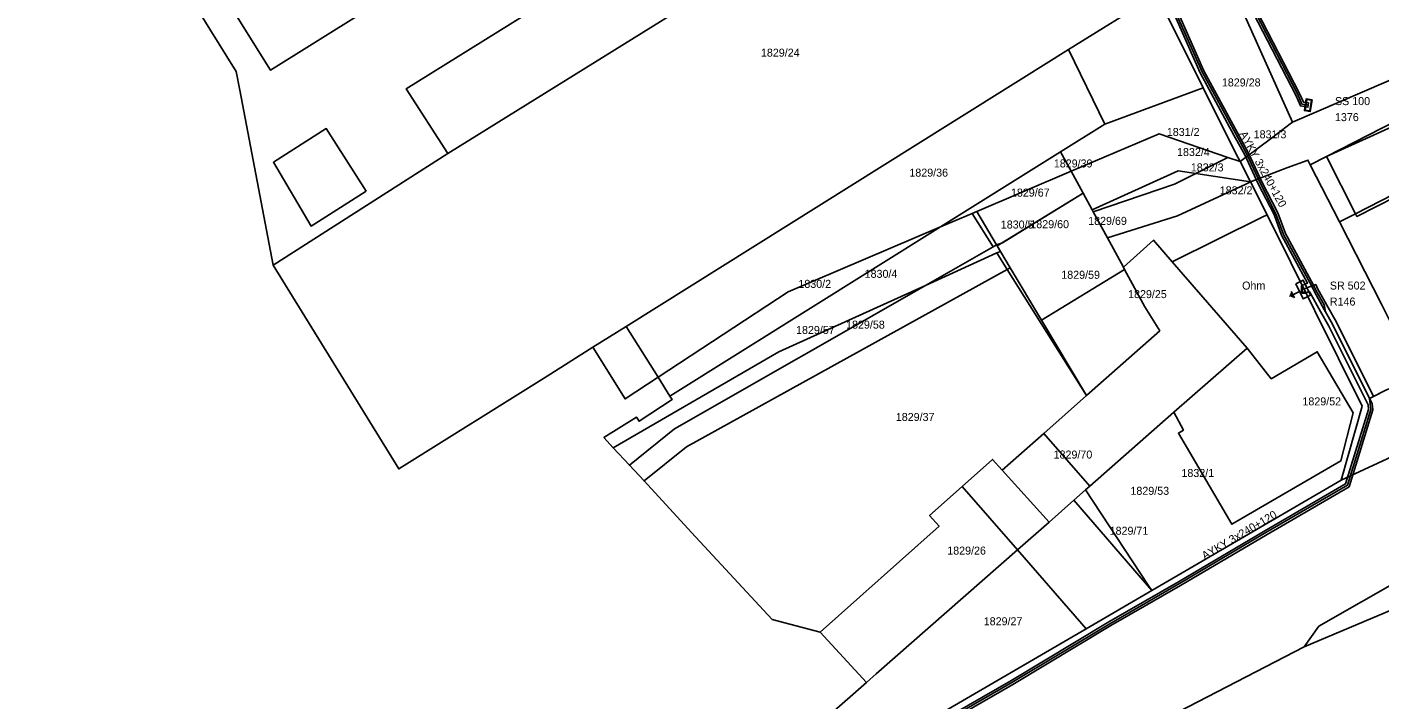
# Model space of a CAD drawing. Extents: x -793400 to -756198, y -1074141 to -1042963.
# Drawn here: x -783799.4 to -783672.6, y -1065170.5 to -1065107.5 of the extents above; entities that cross this region are included whole.
import ezdxf

# ---------------------------------------------------------------- set-up
doc = ezdxf.new("R2010")
doc.units = 0
for name, color, linetype in [('Parcela', 7, 'Continuous'), ('Popiskový text - Parcela', 7, 'Continuous'), ('Popiskový text - Přípojková skříň nn - SJZ', 7, 'Continuous'), ('Popiskový text - Přípojková skříň nn - Typ', 7, 'Continuous'), ('Popiskový text - Rozpojovací skříň nn - SJZ', 7, 'Continuous'), ('Popiskový text - Rozpojovací skříň nn - Typ', 7, 'Continuous'), ('Popiskový text - Uzemnění - Odpor', 7, 'Continuous'), ('Popiskový text - Vedení nn kabelové', 7, 'Continuous'), ('Skříň', 7, 'Continuous'), ('Spojnice nn', 7, 'Continuous'), ('Stavební objekt', 7, 'Continuous'), ('Uzemnění', 7, 'Continuous'), ('Vedení nn kabelové', 7, 'Continuous')]:
    doc.layers.add(name, color=color, linetype=linetype)

msp = doc.modelspace()

# ---------------------------------------------------------------- linework, layer by layer
at = {"layer": 'Parcela'}
for points in [[(-783743.49, -1064990.04), (-783721.39, -1065031.49), (-783712.22, -1065050.17), (-783710.41, -1065053.85), (-783709.53, -1065055.65), (-783703.49, -1065067.95), (-783696.3, -1065082.59), (-783693.78, -1065087.45), (-783688.13, -1065100.02), (-783687.19, -1065102.12), (-783680.77, -1065116.4), (-783681, -1065116.57), (-783682.63, -1065117.8), (-783685.7, -1065120.1), (-783686.08, -1065119.34), (-783689.14, -1065113.18), (-783693.49, -1065104.44), (-783703.53, -1065084.3), (-783706.78, -1065077.78), (-783710.42, -1065070.95), (-783718.74, -1065055.31), (-783724.35, -1065043.92), (-783728.08, -1065036.33), (-783742.64, -1065007.02)], [(-783671.05, -1065116.27), (-783677.6, -1065119.63), (-783679.11, -1065120.41), (-783679.34, -1065119.96), (-783679.42, -1065119.99), (-783681.3, -1065120.7), (-783684.71, -1065122), (-783685.7, -1065120.1), (-783682.63, -1065117.8), (-783681, -1065116.57), (-783680.77, -1065116.4), (-783641.16, -1065099.33)], [(-783658.1, -1065152.09), (-783678.31, -1065163.62), (-783679.68, -1065165.57), (-783702.33, -1065177.28), (-783718.17, -1065186.15), (-783811.05, -1065243.68), (-783813.45, -1065244.74), (-783817.37, -1065243.24), (-783821.65, -1065245.66), (-783820.85, -1065243.75), (-783819.75, -1065241.1), (-783815.59, -1065239.1), (-783811.96, -1065230.63), (-783767.51, -1065209.46), (-783747.03, -1065195.25), (-783744.03, -1065193.23), (-783722.17, -1065178.5), (-783720.51, -1065177.39), (-783721.11, -1065176.1), (-783713.42, -1065171.62), (-783700.12, -1065163.87), (-783693.97, -1065160.29), (-783676.21, -1065149.95), (-783668.48, -1065146.36)], [(-783894.54, -1065298.16), (-783877.6, -1065288.64), (-783876.01, -1065286.99), (-783878.67, -1065284.84), (-783879.31, -1065284.33), (-783882.85, -1065281.51), (-783884.25, -1065280.8), (-783884.72, -1065280.35), (-783886.64, -1065279.77), (-783889.27, -1065279.67), (-783889.47, -1065279.21), (-783885.7, -1065277.91), (-783869.62, -1065270.55), (-783867.95, -1065269.78), (-783847.11, -1065258.93), (-783821.65, -1065245.66), (-783817.37, -1065243.24), (-783813.45, -1065244.74), (-783811.05, -1065243.68), (-783718.17, -1065186.15), (-783702.33, -1065177.28), (-783679.68, -1065165.57), (-783638.54, -1065148.19)]]:
    msp.add_lwpolyline(points, dxfattribs=at)
for points in [[(-783624.81, -1065029.37), (-783608.24, -1065050.49), (-783609.02, -1065051.01), (-783614.97, -1065042.05), (-783620.25, -1065045.55), (-783614.53, -1065054.22), (-783645.96, -1065074.99), (-783640.19, -1065083.64), (-783609.28, -1065062.42), (-783602.2, -1065072.93), (-783596.89, -1065069.32), (-783607.37, -1065053.5), (-783606.59, -1065052.98), (-783598.14, -1065065.66), (-783595.45, -1065069.7), (-783618.75, -1065083), (-783634.61, -1065095.52), (-783641.16, -1065099.33), (-783680.77, -1065116.4), (-783687.19, -1065102.12), (-783688.13, -1065100.02), (-783693.78, -1065087.45), (-783696.3, -1065082.59)], [(-783706.78, -1065077.78), (-783763.85, -1065113.27), (-783759.96, -1065119.35), (-783776.33, -1065129.79), (-783779.45, -1065113.42), (-783779.79, -1065111.66), (-783782.26, -1065107.68), (-783797.2, -1065083.56), (-783794.93, -1065082.14), (-783776.57, -1065111.53), (-783750.64, -1065095.32), (-783756.62, -1065085.78), (-783751.21, -1065082.35), (-783749.58, -1065084.96), (-783741.18, -1065079.7), (-783740.15, -1065081.36), (-783741.89, -1065082.45), (-783738.3, -1065088.24), (-783710.42, -1065070.95)], [(-783693.49, -1065104.44), (-783689.14, -1065113.18), (-783698.37, -1065116.59), (-783701.76, -1065109.61), (-783706.21, -1065112.39), (-783713.05, -1065116.67), (-783743.22, -1065135.54), (-783740.24, -1065140.31), (-783743.33, -1065142.34), (-783746.36, -1065137.5), (-783750.65, -1065140.19), (-783764.55, -1065148.9), (-783776.33, -1065129.79), (-783759.96, -1065119.35), (-783763.85, -1065113.27), (-783706.78, -1065077.78), (-783703.53, -1065084.3)], [(-783728.04, -1065132.29), (-783740.24, -1065140.31), (-783743.22, -1065135.54), (-783713.05, -1065116.67), (-783706.21, -1065112.39), (-783701.76, -1065109.61), (-783698.37, -1065116.59), (-783702.51, -1065119.18), (-783713.76, -1065126.22)], [(-783689.14, -1065113.18), (-783686.08, -1065119.34), (-783685.7, -1065120.1), (-783686.83, -1065119.71), (-783693.27, -1065117.51), (-783701.51, -1065121.01), (-783702.51, -1065119.18), (-783698.37, -1065116.59)], [(-783664.69, -1065115.43), (-783662.2, -1065121.16), (-783668.56, -1065118.67), (-783669.82, -1065116.11), (-783677.6, -1065119.63), (-783671.05, -1065116.27), (-783670.46, -1065116.02), (-783665.66, -1065113.94)], [(-783767.61, -1065122.87), (-783771.34, -1065117.01), (-783776.3, -1065120.16), (-783772.76, -1065126.15)], [(-783668, -1065121.84), (-783666.8, -1065124.7), (-783662.43, -1065122.81), (-783661.97, -1065123.9), (-783659.86, -1065128.84), (-783658.99, -1065128.48), (-783655.16, -1065137.64), (-783661.5, -1065141.32), (-783667.76, -1065126.41), (-783667.4, -1065126.25), (-783669.21, -1065122.45), (-783674.74, -1065125.24), (-783674.87, -1065124.98), (-783676.39, -1065125.75), (-783679.11, -1065120.41), (-783677.6, -1065119.63), (-783669.82, -1065116.11), (-783668.56, -1065118.67), (-783667.19, -1065121.43)], [(-783686.83, -1065119.71), (-783689.84, -1065121.22), (-783691.51, -1065120.97), (-783699.55, -1065124.62), (-783700.4, -1065123.05), (-783701.51, -1065121.01), (-783693.27, -1065117.51)], [(-783700.4, -1065123.05), (-783708.45, -1065128), (-783708.52, -1065127.89), (-783710.37, -1065124.78), (-783710.8, -1065124.96), (-783713.76, -1065126.22), (-783702.51, -1065119.18), (-783701.51, -1065121.01)], [(-783691.85, -1065122.23), (-783699.45, -1065124.81), (-783699.55, -1065124.62), (-783691.51, -1065120.97), (-783689.84, -1065121.22)], [(-783685.7, -1065120.1), (-783684.71, -1065122), (-783689.84, -1065121.22), (-783686.83, -1065119.71)], [(-783668.48, -1065146.36), (-783676.21, -1065149.95), (-783674.25, -1065143), (-783683.17, -1065125.09), (-783684.71, -1065122), (-783681.3, -1065120.7), (-783679.42, -1065119.99), (-783679.34, -1065119.96), (-783679.11, -1065120.41), (-783676.39, -1065125.75), (-783672.45, -1065133.46), (-783671.53, -1065135.28), (-783668.93, -1065140.36), (-783664.13, -1065142.85), (-783663.26, -1065143.94), (-783667.48, -1065145.9)], [(-783691.57, -1065125.19), (-783698.13, -1065127.23), (-783699.45, -1065124.81), (-783691.85, -1065122.23), (-783689.84, -1065121.22), (-783684.71, -1065122), (-783685.15, -1065122.22)], [(-783683.61, -1065125.31), (-783692.06, -1065129.49), (-783693.82, -1065127.46), (-783696.62, -1065130), (-783698.13, -1065127.23), (-783691.57, -1065125.19), (-783685.15, -1065122.22), (-783684.71, -1065122), (-783683.17, -1065125.09)], [(-783696.52, -1065130.2), (-783704.3, -1065134.97), (-783707.23, -1065130.05), (-783708.15, -1065128.51), (-783708.45, -1065128), (-783700.4, -1065123.05), (-783699.55, -1065124.62), (-783699.45, -1065124.81), (-783698.13, -1065127.23), (-783696.62, -1065130)], [(-783669.21, -1065122.45), (-783667.4, -1065126.25), (-783667.76, -1065126.41), (-783661.5, -1065141.32), (-783664.13, -1065142.85), (-783668.93, -1065140.36), (-783671.53, -1065135.28), (-783672.45, -1065133.46), (-783676.39, -1065125.75), (-783674.87, -1065124.98), (-783674.74, -1065125.24)], [(-783708.52, -1065127.89), (-783708.85, -1065128.08), (-783710.8, -1065124.96), (-783710.37, -1065124.78)], [(-783728.92, -1065137.93), (-783744.44, -1065146.92), (-783745.32, -1065145.96), (-783742.26, -1065144.05), (-783742.02, -1065144.43), (-783738.93, -1065142.4), (-783739.13, -1065142.09), (-783713.76, -1065126.22), (-783710.8, -1065124.96), (-783708.85, -1065128.08), (-783715.18, -1065131.7)], [(-783683.17, -1065125.09), (-783674.25, -1065143), (-783676.21, -1065149.95), (-783693.97, -1065160.29), (-783694.31, -1065159.77), (-783700.17, -1065150.86), (-783699.76, -1065150.5), (-783691.89, -1065143.59), (-783691, -1065145.26), (-783691.47, -1065145.54), (-783686.46, -1065154.07), (-783676.25, -1065148.14), (-783675.1, -1065143.65), (-783678.46, -1065137.91), (-783682.77, -1065140.44), (-783685.04, -1065137.58), (-783692.06, -1065129.49), (-783683.61, -1065125.31)], [(-783713.76, -1065126.22), (-783739.13, -1065142.09), (-783740.24, -1065140.31), (-783728.04, -1065132.29)], [(-783708.48, -1065128.66), (-783715.18, -1065131.7), (-783708.85, -1065128.08), (-783708.52, -1065127.89), (-783708.45, -1065128), (-783708.15, -1065128.51)], [(-783707.23, -1065130.05), (-783707.51, -1065130.2), (-783708.48, -1065128.66), (-783708.15, -1065128.51)], [(-783685.04, -1065137.58), (-783682.77, -1065140.44), (-783678.46, -1065137.91), (-783675.1, -1065143.65), (-783676.25, -1065148.14), (-783686.46, -1065154.07), (-783691.47, -1065145.54), (-783691, -1065145.26), (-783691.89, -1065143.59), (-783699.76, -1065150.5), (-783704.09, -1065145.57), (-783700.09, -1065142.03), (-783693.22, -1065135.95), (-783694.61, -1065133.7), (-783696.52, -1065130.2), (-783696.62, -1065130), (-783693.82, -1065127.46), (-783692.06, -1065129.49)], [(-783737.58, -1065146.81), (-783741.56, -1065150.02), (-783742.92, -1065148.55), (-783738.71, -1065145.15), (-783715.18, -1065131.7), (-783708.48, -1065128.66), (-783707.51, -1065130.2)], [(-783704.09, -1065145.57), (-783707.98, -1065149.02), (-783708.89, -1065148.01), (-783711.73, -1065150.54), (-783714.79, -1065153.27), (-783713.9, -1065154.27), (-783725.04, -1065164.2), (-783729.54, -1065163.01), (-783737.1, -1065154.85), (-783741.56, -1065150.02), (-783737.58, -1065146.81), (-783707.51, -1065130.2), (-783700.09, -1065142.03)], [(-783704.3, -1065134.97), (-783700.09, -1065142.03), (-783707.51, -1065130.2), (-783707.23, -1065130.05)], [(-783693.22, -1065135.95), (-783700.09, -1065142.03), (-783704.3, -1065134.97), (-783696.52, -1065130.2), (-783694.61, -1065133.7)], [(-783738.71, -1065145.15), (-783742.92, -1065148.55), (-783744.44, -1065146.92), (-783728.92, -1065137.93), (-783715.18, -1065131.7)], [(-783704.09, -1065145.57), (-783699.76, -1065150.5), (-783700.17, -1065150.86), (-783701.26, -1065151.82), (-783703.6, -1065153.87), (-783706.56, -1065156.47), (-783711.73, -1065150.54), (-783708.89, -1065148.01), (-783707.98, -1065149.02)], [(-783638.54, -1065148.19), (-783679.68, -1065165.57), (-783678.31, -1065163.62), (-783658.1, -1065152.09), (-783638.24, -1065146.37)], [(-783719.81, -1065168.1), (-783720.72, -1065168.9), (-783725.04, -1065164.2), (-783713.9, -1065154.27), (-783714.79, -1065153.27), (-783711.73, -1065150.54), (-783706.56, -1065156.47)], [(-783694.31, -1065159.77), (-783693.97, -1065160.29), (-783694.38, -1065159.81), (-783701.26, -1065151.82), (-783700.17, -1065150.86)], [(-783693.97, -1065160.29), (-783700.12, -1065163.87), (-783700.52, -1065163.41), (-783706.56, -1065156.47), (-783703.6, -1065153.87), (-783701.26, -1065151.82), (-783694.38, -1065159.81)], [(-783713.42, -1065171.62), (-783721.11, -1065176.1), (-783721.36, -1065175.66), (-783723.31, -1065174.64), (-783725.03, -1065172.69), (-783720.72, -1065168.9), (-783719.81, -1065168.1), (-783706.56, -1065156.47), (-783700.52, -1065163.41), (-783700.12, -1065163.87)]]:
    msp.add_lwpolyline(points, close=True, dxfattribs=at)
at = {"layer": 'Skříň'}
for points in [[(-783678.94, -1065114.3), (-783679.11, -1065115.41), (-783679.66, -1065115.32), (-783679.49, -1065114.21)], [(-783679.16, -1065115.34), (-783679, -1065114.34), (-783679.45, -1065114.28), (-783679.6, -1065115.28)], [(-783680.48, -1065131.55), (-783679.79, -1065132.97), (-783679.08, -1065132.63), (-783679.77, -1065131.21)]]:
    msp.add_lwpolyline(points, close=True, dxfattribs=at)
at = {"layer": 'Spojnice nn'}
for points in [[(-783695.55, -1065082.08), (-783694.73, -1065084.09), (-783693.68, -1065086.85), (-783689.18, -1065095.9), (-783684.26, -1065106.14), (-783680.29, -1065113.8), (-783679.9, -1065114.71), (-783679.3, -1065114.81)], [(-783678.98, -1065131.76), (-783681.62, -1065126.92), (-783682.33, -1065124.98), (-783683.82, -1065122.09), (-783685.07, -1065119.39), (-783686.1, -1065117.51), (-783689.26, -1065111.69), (-783692.11, -1065105.25), (-783692.55, -1065104.45), (-783693.66, -1065102.53)], [(-783679.78, -1065132.09), (-783679.38, -1065131.91), (-783678.98, -1065131.76)], [(-783673.55, -1065142.29), (-783677.02, -1065135.34), (-783677.8, -1065133.95), (-783678.76, -1065132.23), (-783678.98, -1065131.76)], [(-783673.55, -1065142.29), (-783671.98, -1065141.48), (-783670, -1065140.7), (-783669.05, -1065140.63), (-783668.38, -1065141.25), (-783666.53, -1065142.74), (-783664.64, -1065143.29), (-783663.56, -1065143.27), (-783662.58, -1065142.79), (-783659.29, -1065140.97), (-783656.19, -1065138.98), (-783654.94, -1065138.51)], [(-783719.19, -1065175.88), (-783707.08, -1065168.91), (-783697.91, -1065163.4), (-783691.38, -1065159.63), (-783683.27, -1065154.86), (-783675.63, -1065150.43), (-783673.45, -1065143.34), (-783673.55, -1065142.29)]]:
    msp.add_lwpolyline(points, dxfattribs=at)
at = {"layer": 'Stavební objekt'}
for points in [[(-783750.65, -1065140.19), (-783764.55, -1065148.9), (-783776.33, -1065129.79), (-783759.96, -1065119.35), (-783703.53, -1065084.3), (-783693.49, -1065104.44), (-783701.76, -1065109.61), (-783706.21, -1065112.39), (-783713.05, -1065116.67), (-783743.22, -1065135.54), (-783746.36, -1065137.5)], [(-783667.74, -1065121.34), (-783674.87, -1065124.98), (-783677.6, -1065119.63), (-783671.05, -1065116.27), (-783670.46, -1065116.02), (-783669.24, -1065118.4)], [(-783707.96, -1065127.7), (-783708.52, -1065127.89), (-783710.37, -1065124.78), (-783701.51, -1065121.01), (-783700.4, -1065123.05)], [(-783696.52, -1065130.2), (-783704.3, -1065134.97), (-783707.23, -1065130.05), (-783708.15, -1065128.51), (-783708.45, -1065128), (-783700.4, -1065123.05), (-783699.55, -1065124.62), (-783699.45, -1065124.81), (-783698.13, -1065127.23), (-783696.62, -1065130)], [(-783691.89, -1065143.59), (-783699.76, -1065150.5), (-783704.09, -1065145.57), (-783700.09, -1065142.03), (-783693.22, -1065135.95), (-783694.61, -1065133.7), (-783696.52, -1065130.2), (-783696.62, -1065130), (-783693.82, -1065127.46), (-783692.06, -1065129.49), (-783685.04, -1065137.58)], [(-783693.22, -1065135.95), (-783700.09, -1065142.03), (-783704.3, -1065134.97), (-783696.52, -1065130.2), (-783694.61, -1065133.7)], [(-783701.26, -1065151.82), (-783703.6, -1065153.87), (-783707.98, -1065149.02), (-783704.09, -1065145.57), (-783699.76, -1065150.5), (-783700.17, -1065150.86)], [(-783719.81, -1065168.1), (-783720.72, -1065168.9), (-783725.04, -1065164.2), (-783713.9, -1065154.27), (-783714.79, -1065153.27), (-783711.73, -1065150.54), (-783706.56, -1065156.47)]]:
    msp.add_lwpolyline(points, close=True, dxfattribs=at)
at = {"layer": 'Uzemnění'}
for p, q in [((-783680.9, -1065132.26), (-783680.59, -1065132.88)), ((-783680.13, -1065132.27), (-783680.74, -1065132.57)), ((-783681.03, -1065132.66), (-783680.99, -1065132.75)), ((-783680.98, -1065132.53), (-783680.85, -1065132.78)), ((-783680.93, -1065132.42), (-783680.73, -1065132.81))]:
    msp.add_line(p, q, dxfattribs=at)
at = {"layer": 'Vedení nn kabelové'}
for points in [[(-783679.3, -1065114.81), (-783679.27, -1065114.61), (-783679.76, -1065114.53), (-783680.11, -1065113.71), (-783684.08, -1065106.05), (-783689, -1065095.81), (-783693.5, -1065086.77), (-783694.54, -1065084.02), (-783695.36, -1065082.01), (-783695.51, -1065081.48), (-783695.22, -1065081.24), (-783694.99, -1065081.24), (-783694.99, -1065081.03)], [(-783695.74, -1065082.15), (-783694.92, -1065084.16), (-783693.86, -1065086.93), (-783689.36, -1065095.99), (-783684.44, -1065106.23), (-783680.47, -1065113.89), (-783680.04, -1065114.89), (-783679.33, -1065115.01), (-783679.3, -1065114.81)], [(-783679.61, -1065132.18), (-783679.61, -1065132.33), (-783679.94, -1065132.33), (-783679.94, -1065131.73), (-783679.53, -1065131.54), (-783679.36, -1065131.48), (-783681.8, -1065127), (-783682.51, -1065125.06), (-783684, -1065122.18), (-783685.25, -1065119.48), (-783686.28, -1065117.61), (-783689.44, -1065111.78), (-783692.29, -1065105.34), (-783692.72, -1065104.55), (-783693.57, -1065103.08), (-783693.7, -1065103.08), (-783693.78, -1065103.08), (-783694.06, -1065102.72)], [(-783719.09, -1065176.05), (-783706.98, -1065169.08), (-783697.81, -1065163.57), (-783691.28, -1065159.8), (-783683.17, -1065155.03), (-783675.46, -1065150.56), (-783673.25, -1065143.36), (-783673.3, -1065142.79), (-783677.02, -1065135.34), (-783677.68, -1065134.17), (-783677.8, -1065133.53), (-783678.58, -1065132.14), (-783678.8, -1065131.67), (-783681.44, -1065126.84), (-783682.15, -1065124.9), (-783683.64, -1065122), (-783684.89, -1065119.3), (-783685.92, -1065117.41), (-783689.08, -1065111.6), (-783691.93, -1065105.16)], [(-783679.64, -1065132.18), (-783679.64, -1065132.38), (-783679.45, -1065132.38), (-783679.23, -1065132.28), (-783679.19, -1065132.26), (-783679.12, -1065132.41), (-783678.15, -1065134.14), (-783677.37, -1065135.53), (-783673.69, -1065142.9), (-783673.65, -1065143.32), (-783675.8, -1065150.3), (-783683.37, -1065154.69), (-783691.48, -1065159.46), (-783698.01, -1065163.23), (-783707.18, -1065168.74), (-783719.29, -1065175.71)], [(-783654.94, -1065138.51), (-783656.19, -1065138.98), (-783659.29, -1065140.97), (-783662.58, -1065142.79), (-783663.56, -1065143.27), (-783664.64, -1065143.29), (-783666.53, -1065142.74), (-783668.38, -1065141.25), (-783669.05, -1065140.63), (-783670, -1065140.7), (-783671.98, -1065141.48), (-783673.19, -1065142.11), (-783676.67, -1065135.15), (-783677.44, -1065133.77), (-783678.4, -1065132.05), (-783678.6, -1065131.62), (-783679.38, -1065131.91), (-783679.66, -1065132.03), (-783679.88, -1065132.03), (-783679.88, -1065132.42), (-783679.58, -1065132.42), (-783679.58, -1065132.18)]]:
    msp.add_lwpolyline(points, dxfattribs=at)

# ---------------------------------------------------------------- texts
at = {"layer": 'Popiskový text - Parcela'}
for s, p in [('1829/24', (-783730.6, -1065110.27)), ('1829/28', (-783687.4, -1065113.06)), ('1831/2', (-783692.56, -1065117.7)), ('1831/3', (-783684.42, -1065117.92)), ('1832/4', (-783691.6, -1065119.58)), ('1829/36', (-783716.69, -1065121.51)), ('1829/39', (-783703.15, -1065120.65)), ('1832/3', (-783690.31, -1065121.02)), ('1829/67', (-783707.17, -1065123.38)), ('1832/2', (-783687.6, -1065123.17)), ('1830/5', (-783708.12, -1065126.37)), ('1829/60', (-783705.35, -1065126.34)), ('1829/69', (-783699.93, -1065126.03)), ('1830/4', (-783720.88, -1065130.99)), ('1829/59', (-783702.45, -1065131.08)), ('1830/2', (-783727.09, -1065131.93)), ('1829/25', (-783696.19, -1065132.89)), ('1829/57', (-783727.31, -1065136.25)), ('1829/58', (-783722.62, -1065135.75)), ('1829/52', (-783679.85, -1065142.94)), ('1829/37', (-783717.96, -1065144.4)), ('1829/70', (-783703.17, -1065147.92)), ('1832/1', (-783691.19, -1065149.65)), ('1829/53', (-783695.97, -1065151.32)), ('1829/71', (-783697.92, -1065155.06)), ('1829/26', (-783713.14, -1065156.92)), ('1829/27', (-783709.72, -1065163.54))]:
    msp.add_text(s, height=0.75, dxfattribs=at).set_placement(p)
at = {"layer": 'Popiskový text - Přípojková skříň nn - SJZ'}
msp.add_text('1376', height=0.75, dxfattribs=at).set_placement((-783676.8, -1065116.31))
at = {"layer": 'Popiskový text - Přípojková skříň nn - Typ'}
msp.add_text('SS 100', height=0.75, dxfattribs=at).set_placement((-783676.8, -1065114.81))
at = {"layer": 'Popiskový text - Rozpojovací skříň nn - SJZ'}
msp.add_text('R146', height=0.75, dxfattribs=at).set_placement((-783677.28, -1065133.59))
at = {"layer": 'Popiskový text - Rozpojovací skříň nn - Typ'}
msp.add_text('SR 502', height=0.75, dxfattribs=at).set_placement((-783677.28, -1065132.09))
at = {"layer": 'Popiskový text - Uzemnění - Odpor'}
msp.add_text(' Ohm', height=0.75, dxfattribs=at).set_placement((-783685.78, -1065132.09))
at = {"layer": 'Popiskový text - Vedení nn kabelové'}
for rotation, p in [(298.7402, (-783685.77, -1065117.5)), (30.4814, (-783689.01, -1065157.42))]:
    msp.add_text('AYKY 3x240+120', height=0.75, rotation=rotation, dxfattribs=at).set_placement(p)

doc.saveas('drawing.dxf')
